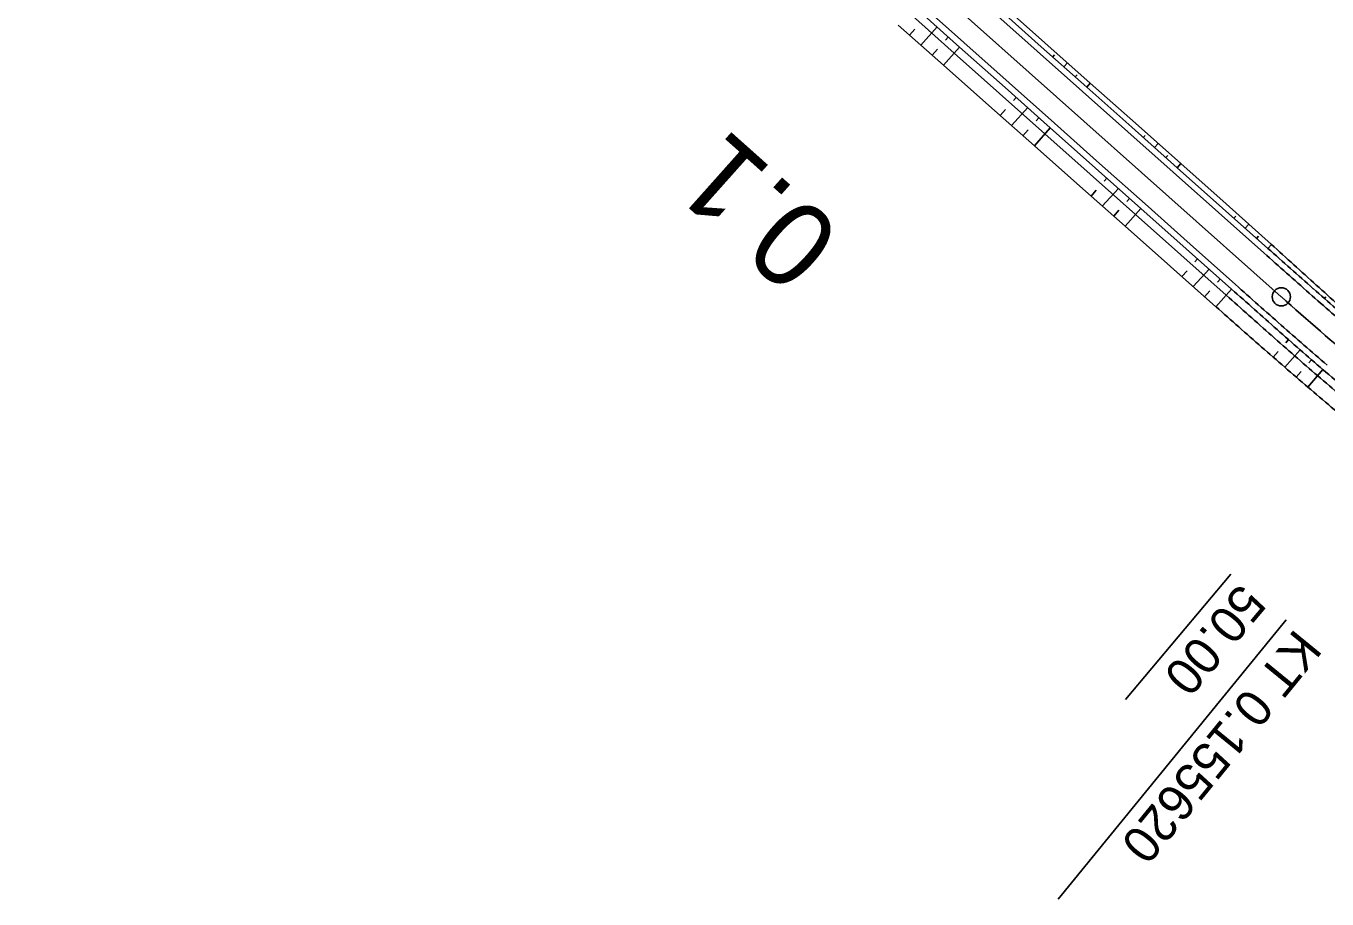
# Model space of a CAD drawing. Extents: x -481645 to -478728, y -1113199 to -1110710.
# Drawn here: x -480958.5 to -480851.3, y -1112720.7 to -1112648.7 of the extents above; entities that cross this region are included whole.
import ezdxf

# ---------------------------------------------------------------- set-up
doc = ezdxf.new("R2010")
doc.units = 0
for name, color, linetype in [('CP14_HATCH_SLOPE_R', 7, 'Continuous'), ('Vrstva 31', 7, 'Continuous'), ('Vrstva 32', 7, 'Continuous'), ('Vrstva 33', 7, 'Continuous'), ('Vrstva 34', 7, 'Continuous'), ('Vrstva 35', 7, 'Continuous'), ('Vrstva 36', 7, 'Continuous'), ('Vrstva 37', 7, 'Continuous'), ('Vrstva 38', 7, 'Continuous'), ('Vrstva 39', 7, 'Continuous'), ('Vrstva 40', 7, 'Continuous')]:
    doc.layers.add(name, color=color, linetype=linetype)

msp = doc.modelspace()

# ---------------------------------------------------------------- linework, layer by layer
at = {"layer": 'CP14_HATCH_SLOPE_R'}
msp.add_line((-480958.52, -1112578.96), (-480855.08, -1112671.03), dxfattribs=at)
msp.add_arc((-480589.13, -1112372.25), 400, 228.3273, 230.7827, dxfattribs=at)
at = {"layer": 'Vrstva 31'}
for p, q in [((-480878.31, -1112646.77), (-480874.57, -1112650.09)), ((-480886.66, -1112648.63), (-480882.92, -1112651.95)), ((-480874.57, -1112650.09), (-480870.83, -1112653.41)), ((-480882.92, -1112651.95), (-480879.18, -1112655.27)), ((-480870.83, -1112653.41), (-480867.09, -1112656.73)), ((-480879.18, -1112655.27), (-480875.43, -1112658.58)), ((-480867.09, -1112656.73), (-480863.35, -1112660.05)), ((-480875.43, -1112658.58), (-480871.69, -1112661.9)), ((-480863.35, -1112660.05), (-480859.62, -1112663.37)), ((-480871.69, -1112661.9), (-480867.96, -1112665.22)), ((-480859.62, -1112663.37), (-480855.9, -1112666.71)), ((-480867.96, -1112665.22), (-480864.21, -1112668.54)), ((-480864.21, -1112668.54), (-480860.47, -1112671.85))]:
    msp.add_line(p, q, dxfattribs=at)
for centre, radius, start, end in [((-480053.29, -1111785.29), 1192.09, 227.67959, 227.91944), ((-480585.59, -1112375.38), 397.39, 227.8632, 228.5795), ((-480056.05, -1111764.59), 1212.52, 228.43858, 228.6756), ((-480590.26, -1112371.27), 404.16, 228.7574, 229.4736), ((-480590.12, -1112371.41), 404.15, 229.4449, 230.1611)]:
    msp.add_arc(centre, radius, start, end, dxfattribs=at)
at = {"layer": 'Vrstva 32'}
for p, q in [((-480885.76, -1112647.63), (-480882.03, -1112650.95)), ((-480882.03, -1112650.95), (-480878.29, -1112654.27)), ((-480878.29, -1112654.27), (-480874.56, -1112657.6)), ((-480874.56, -1112657.6), (-480870.82, -1112660.92)), ((-480870.82, -1112660.92), (-480867.09, -1112664.25)), ((-480867.09, -1112664.25), (-480863.35, -1112667.57)), ((-480863.35, -1112667.57), (-480859.62, -1112670.9))]:
    msp.add_line(p, q, dxfattribs=at)
for centre, radius, start, end in [((-480054.61, -1111769.21), 1208.75, 228.2419, 228.47943), ((-480589.13, -1112372.25), 402.92, 228.5453, 229.2615), ((-480589.13, -1112372.25), 402.92, 229.2615, 229.9777)]:
    msp.add_arc(centre, radius, start, end, dxfattribs=at)
at = {"layer": 'Vrstva 33'}
for p, q in [((-480885.32, -1112647.13), (-480881.59, -1112650.45)), ((-480878.59, -1112647.09), (-480874.86, -1112650.42)), ((-480881.59, -1112650.45), (-480877.85, -1112653.78)), ((-480874.86, -1112650.42), (-480871.12, -1112653.74)), ((-480877.85, -1112653.78), (-480874.12, -1112657.1)), ((-480871.12, -1112653.74), (-480867.39, -1112657.06)), ((-480874.12, -1112657.1), (-480870.38, -1112660.43)), ((-480867.39, -1112657.06), (-480863.66, -1112660.39)), ((-480870.38, -1112660.43), (-480866.65, -1112663.75)), ((-480863.66, -1112660.39), (-480859.92, -1112663.71)), ((-480866.65, -1112663.75), (-480862.91, -1112667.07)), ((-480859.92, -1112663.71), (-480856.18, -1112667.04)), ((-480862.91, -1112667.07), (-480859.18, -1112670.4))]:
    msp.add_line(p, q, dxfattribs=at)
for centre, radius, start, end in [((-480061.47, -1111776.94), 1193.25, 228.24053, 228.4802), ((-480055.49, -1111770.21), 1206.75, 228.24172, 228.47953), ((-480589.13, -1112372.25), 397.75, 228.5453, 229.2615), ((-480589.13, -1112372.25), 402.25, 228.5453, 229.2615), ((-480589.13, -1112372.25), 402.25, 229.2615, 229.9777)]:
    msp.add_arc(centre, radius, start, end, dxfattribs=at)
at = {"layer": 'Vrstva 34'}
for p, q in [((-480884.99, -1112646.76), (-480881.25, -1112650.08)), ((-480878.93, -1112647.47), (-480875.19, -1112650.79)), ((-480881.25, -1112650.08), (-480877.52, -1112653.4)), ((-480875.19, -1112650.79), (-480871.46, -1112654.11)), ((-480877.52, -1112653.4), (-480873.78, -1112656.73)), ((-480871.46, -1112654.11), (-480867.72, -1112657.44)), ((-480873.78, -1112656.73), (-480870.05, -1112660.05)), ((-480867.72, -1112657.44), (-480863.99, -1112660.76)), ((-480870.05, -1112660.05), (-480866.31, -1112663.38)), ((-480863.99, -1112660.76), (-480860.25, -1112664.09)), ((-480866.31, -1112663.38), (-480862.58, -1112666.7)), ((-480860.25, -1112664.09), (-480856.52, -1112667.41)), ((-480862.58, -1112666.7), (-480858.85, -1112670.02))]:
    msp.add_line(p, q, dxfattribs=at)
for centre, radius, start, end in [((-480060.81, -1111776.19), 1194.75, 228.24066, 228.48013), ((-480056.16, -1111770.96), 1205.25, 228.24159, 228.4796), ((-480589.13, -1112372.25), 398.25, 228.5453, 229.2615), ((-480589.13, -1112372.25), 401.75, 228.5453, 229.2615)]:
    msp.add_arc(centre, radius, start, end, dxfattribs=at)
at = {"layer": 'Vrstva 35'}
for p, q in [((-480884.99, -1112646.76), (-480881.25, -1112650.08)), ((-480878.93, -1112647.47), (-480875.19, -1112650.79)), ((-480881.25, -1112650.08), (-480877.52, -1112653.4)), ((-480875.19, -1112650.79), (-480871.46, -1112654.11)), ((-480877.52, -1112653.4), (-480873.78, -1112656.73)), ((-480871.46, -1112654.11), (-480867.72, -1112657.44)), ((-480873.78, -1112656.73), (-480870.05, -1112660.05)), ((-480867.72, -1112657.44), (-480863.99, -1112660.76)), ((-480870.05, -1112660.05), (-480866.31, -1112663.38)), ((-480863.99, -1112660.76), (-480860.25, -1112664.09)), ((-480866.31, -1112663.38), (-480862.58, -1112666.7)), ((-480860.25, -1112664.09), (-480856.52, -1112667.41)), ((-480862.58, -1112666.7), (-480858.85, -1112670.02))]:
    msp.add_line(p, q, dxfattribs=at)
for centre, radius, start, end in [((-480060.81, -1111776.19), 1194.75, 228.24066, 228.48013), ((-480056.16, -1111770.96), 1205.25, 228.24159, 228.4796), ((-480589.13, -1112372.25), 398.25, 228.5453, 229.2615), ((-480589.13, -1112372.25), 401.75, 228.5453, 229.2615)]:
    msp.add_arc(centre, radius, start, end, dxfattribs=at)
at = {"layer": 'Vrstva 36'}
msp.add_line((-480859.23, -1112693.88), (-480867.91, -1112704.22), dxfattribs=at)
at = {"layer": 'Vrstva 37'}
msp.add_line((-480854.68, -1112697.65), (-480873.46, -1112720.66), dxfattribs=at)
msp.add_circle((-480855.08, -1112671.03), 0.75, dxfattribs=at)
at = {"layer": 'Vrstva 39'}
for p, q in [((-480873.92, -1112651.25), (-480873.78, -1112651.08)), ((-480873.64, -1112650.92), (-480873.64, -1112650.92)), ((-480872.99, -1112652.08), (-480872.7, -1112651.75)), ((-480872.06, -1112652.91), (-480871.91, -1112652.74)), ((-480871.77, -1112652.58), (-480871.77, -1112652.58)), ((-480871.12, -1112653.74), (-480870.83, -1112653.41)), ((-480866.46, -1112657.9), (-480866.31, -1112657.73)), ((-480866.16, -1112657.56), (-480866.16, -1112657.56)), ((-480865.52, -1112658.73), (-480865.22, -1112658.39)), ((-480864.29, -1112659.22), (-480864.29, -1112659.22)), ((-480864.59, -1112659.56), (-480864.44, -1112659.39)), ((-480863.66, -1112660.39), (-480863.35, -1112660.05)), ((-480858.99, -1112664.54), (-480858.84, -1112664.38)), ((-480858.69, -1112664.21), (-480858.69, -1112664.21)), ((-480858.05, -1112665.38), (-480857.76, -1112665.04)), ((-480857.12, -1112666.21), (-480856.97, -1112666.04)), ((-480856.83, -1112665.88), (-480856.83, -1112665.88)), ((-480856.18, -1112667.04), (-480855.9, -1112666.71)), ((-480851.52, -1112671.18), (-480851.4, -1112671.03))]:
    msp.add_line(p, q, dxfattribs=at)
at = {"layer": 'Vrstva 40'}
for p, q in [((-480885.28, -1112648.96), (-480885.73, -1112649.46)), ((-480883.45, -1112648.79), (-480884.79, -1112650.29)), ((-480883.41, -1112650.62), (-480883.85, -1112651.12)), ((-480881.59, -1112650.45), (-480882.92, -1112651.95)), ((-480882.52, -1112649.62), (-480882.74, -1112649.87)), ((-480876.92, -1112654.61), (-480877.14, -1112654.86)), ((-480877.8, -1112655.6), (-480878.24, -1112656.09)), ((-480875.98, -1112655.44), (-480877.31, -1112656.92)), ((-480874.12, -1112657.1), (-480875.43, -1112658.58)), ((-480875.05, -1112656.27), (-480875.27, -1112656.52)), ((-480875.93, -1112657.26), (-480876.37, -1112657.75)), ((-480869.45, -1112661.26), (-480869.67, -1112661.51)), ((-480870.33, -1112662.24), (-480870.76, -1112662.73)), ((-480868.51, -1112662.09), (-480869.83, -1112663.56)), ((-480867.58, -1112662.92), (-480867.8, -1112663.17)), ((-480868.46, -1112663.9), (-480868.89, -1112664.39)), ((-480866.65, -1112663.75), (-480867.96, -1112665.22)), ((-480862.85, -1112668.88), (-480863.28, -1112669.36)), ((-480861.04, -1112668.74), (-480862.34, -1112670.19)), ((-480861.98, -1112667.91), (-480862.2, -1112668.15)), ((-480860.11, -1112669.57), (-480860.33, -1112669.82)), ((-480860.98, -1112670.54), (-480861.4, -1112671.02)), ((-480859.18, -1112670.4), (-480860.47, -1112671.85)), ((-480854.49, -1112674.56), (-480854.71, -1112674.81)), ((-480855.34, -1112675.53), (-480855.76, -1112676)), ((-480853.54, -1112675.39), (-480854.8, -1112676.83)), ((-480852.6, -1112676.21), (-480852.81, -1112676.46)), ((-480853.44, -1112677.18), (-480853.85, -1112677.65)), ((-480851.65, -1112677.03), (-480852.89, -1112678.47))]:
    msp.add_line(p, q, dxfattribs=at)

# ---------------------------------------------------------------- texts
at = {"layer": 'Vrstva 36'}
msp.add_text('50.00', height=2.999, rotation=229.9777, dxfattribs=at).set_placement((-480858.46, -1112694.52))
at = {"layer": 'Vrstva 37'}
msp.add_text('KT 0.155620', height=3, rotation=230.7828, dxfattribs=at).set_placement((-480853.91, -1112698.28))
at = {"layer": 'Vrstva 38'}
msp.add_text('0.1', height=6.999, rotation=138.2817, dxfattribs=at).set_placement((-480891.03, -1112665.82))

doc.saveas('drawing.dxf')
